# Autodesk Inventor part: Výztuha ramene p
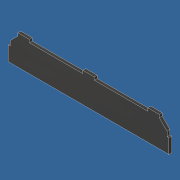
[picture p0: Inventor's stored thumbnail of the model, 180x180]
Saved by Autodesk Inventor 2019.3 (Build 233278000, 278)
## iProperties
Created: 2019-02
Part Number: Výztuha ramene p
Material: Nerezová ocel, austenitická
Document SubType Name: Modeling
Designer: B-hon
Density: 8 g/cm^3
Appearance: Tmavě šedá
Author: B-hon
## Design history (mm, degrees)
sketch "Náčrt1"
  geometry: L1 (0, 0)-(167, 0); L2 (167, 0)-(167, 31); L3 (167, 31)-(0, 31); L4 (0, 31)-(0, 0)
  constraints: 8 end point, 2 parallel, 1 horizontal, 1 perpendicular
  dimensions: "d0" = 167 distance of L3.end L2.end; "d1" = 31 distance of L2.end L1.end
extrude "Vysunutí1" new body sketch "Náčrt1" distance "d2" = 3; taper "d3" = 0 deg
sketch "Náčrt2"
  geometry: L1 (-5.629, 40.214)-(2, 40.214); L2 (2, 40.214)-(2, 15); L3 (2, 15)-(-5.629, 15); L4 (-5.629, 15)-(-5.629, 40.214); L5 (0, 0)-(167, 0) reference; L6 (0, 31)-(0, 0) reference; L7 (165, 47.584)-(218.204, 47.584); L8 (218.204, 47.584)-(218.204, 15); L9 (218.204, 15)-(165, 15); L10 (165, 15)-(165, 47.584); L11 (167, 0)-(167, 31) reference
  constraints: 16 end point, 4 parallel, 2 horizontal, 2 perpendicular
  dimensions: "d4" = 15 distance between parallel lines of L5 L3; "d5" = 2 distance between parallel lines of L6 L2; "d6" = 15 distance between parallel lines of L5 L9; "d7" = 2 distance between parallel lines of L11 L10
extrude "Vysunutí2" cut sketch "Náčrt2" distance "d8" = 3; taper "d9" = 0 deg
sketch "Náčrt3"
  geometry: L1 (145, 44.218)-(89.5, 44.218); L2 (89.5, 44.218)-(89.5, 28); L3 (89.5, 28)-(145, 28); L4 (145, 28)-(145, 44.218); L5 (77.5, 39.969)-(22, 39.969); L6 (22, 39.969)-(22, 28); L7 (22, 28)-(77.5, 28); L8 (77.5, 28)-(77.5, 39.969); L9 (167, 0)-(167, 15) reference; L10 (165, 31)-(2, 31) reference; L11 (0, 15)-(0, 0) reference; L12 (2, 31)-(2, 15) reference
  constraints: 16 end point, 4 parallel, 2 horizontal, 2 perpendicular
  dimensions: "d11" = 3 distance between parallel lines of L10 L3; "d12" = 55.5 distance of L2.end L3.end; "d14" = 55.5 distance of L6.end L7.end; "d15" = 3 distance between parallel lines of L10 L7; "d26" = 12 distance between parallel lines of L2 L8; "d27" = 20 distance between parallel lines of L12 L6
extrude "Vysunutí3" cut sketch "Náčrt3" distance "d16" = 3; taper "d17" = 0 deg
sketch "Náčrt4"
  geometry: L1 (-11.66, 39.496)-(10, 39.496); L2 (10, 39.496)-(10, 28); L3 (10, 28)-(-11.66, 28); L4 (-11.66, 28)-(-11.66, 39.496); L5 (218.41, 46.602)-(157, 46.602); L6 (157, 46.602)-(157, 28); L7 (157, 28)-(218.41, 28); L8 (218.41, 28)-(218.41, 46.602); L9 (22, 31)-(2, 31) reference; L10 (22, 28)-(22, 31) reference; L11 (145, 31)-(145, 28) reference; 1 further point
  constraints: 16 end point, 4 parallel, 2 horizontal, 2 perpendicular, 1 point on line
  dimensions: "d18" = 3 distance between parallel lines of L9 L3; "d19" = 12 distance between parallel lines of L10 L2; "d20" = 12 distance between parallel lines of L11 L6
extrude "Vysunutí4" cut sketch "Náčrt4" distance "d21" = 3; taper "d22" = 0 deg
chamfer "Zkosení2" distance "d28" = 8; stored, may be unused: second distance "d29" = 2, angle "d30" = 45 deg
node "Těleso1"
